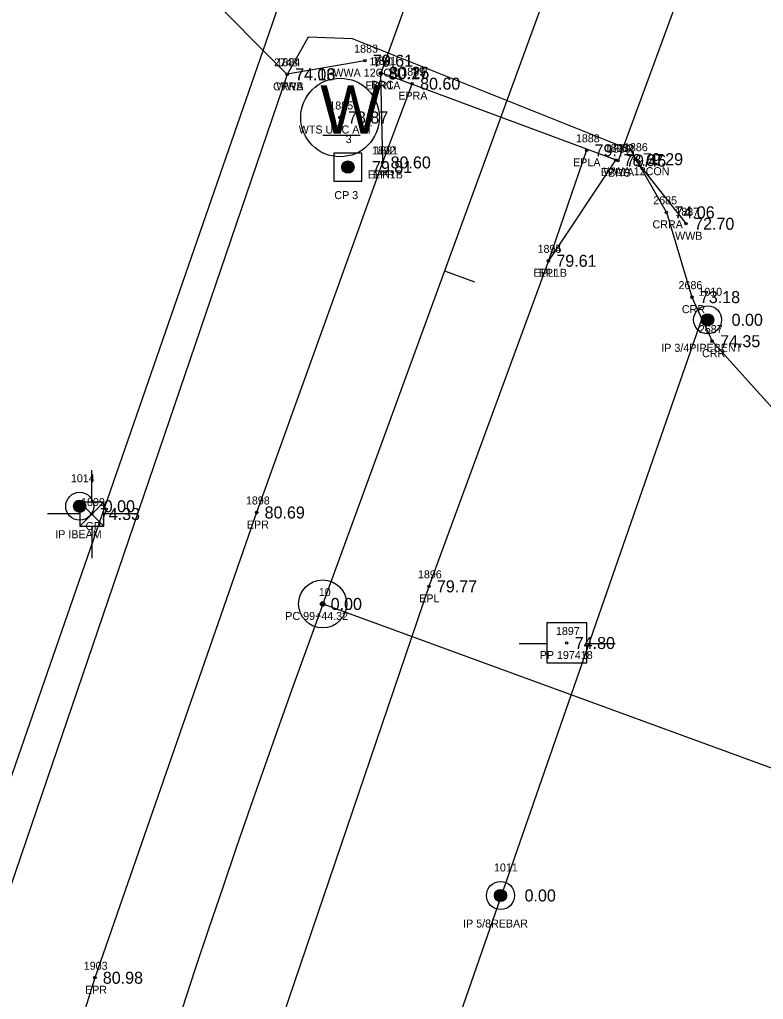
# Model space of a CAD drawing. Extents: x 2139392 to 2143384, y 505395 to 510520.
# Drawn here: x 2140632.7 to 2140725.6, y 508219 to 508341.4 of the extents above; entities that cross this region are included whole.
import ezdxf

# ---------------------------------------------------------------- set-up
doc = ezdxf.new("R2010")
doc.units = 0
for name, color, linetype in [('RD_EV_EX_Wetlands', 7, 'Continuous'), ('RD_EX_Bridge', 7, 'Continuous'), ('RD_EX_Bridge_txCode', 7, 'Continuous'), ('RD_EX_DV_Prop_txCode', 7, 'Continuous'), ('RD_EX_DV_PropPin', 7, 'Continuous'), ('RD_EX_H2O', 7, 'Continuous'), ('RD_EX_H2O_txCode', 7, 'Continuous'), ('RD_EX_Road', 7, 'Continuous'), ('RD_EX_Road_txCode', 7, 'Continuous'), ('RD_EX_TX_Bridge_ELEV', 7, 'Continuous'), ('RD_EX_TX_DV_Prop_ELEV', 7, 'Continuous'), ('RD_EX_TX_H2O_ELEV', 7, 'Continuous'), ('RD_EX_TX_Road_ELEV', 7, 'Continuous'), ('RD_EX_TX_UT_ELEV', 7, 'Continuous'), ('RD_EX_UT', 7, 'Continuous'), ('RD_EX_UT_txCode', 7, 'Continuous'), ('RD_EX_VEG', 7, 'Continuous'), ('RD_HC_Cl', 7, 'Continuous'), ('RD_HC_Data', 7, 'Continuous'), ('RD_HC_Data_Tic', 7, 'Continuous'), ('RD_HC_Survey', 7, 'Continuous'), ('RD_HC_Survey_ELEV', 7, 'Continuous'), ('RD_HC_Survey_txCode', 7, 'Continuous'), ('RD_HC_txCode', 7, 'Continuous'), ('RD_SMD_Locator', 7, 'Continuous')]:
    doc.layers.add(name, color=color, linetype=linetype)

msp = doc.modelspace()

# ---------------------------------------------------------------- linework, layer by layer
at = {"layer": 'RD_EV_EX_Wetlands'}
for points in [[(2141075.3, 509306.14), (2141106.63, 509288.93), (2141187.92, 509247.51), (2140965, 508598.64), (2140811.93, 508219.91), (2140776.47, 508059.54), (2140705.92, 508079.01), (2140681.94, 508086.65), (2140661.45, 508087.99), (2140646.39, 508098.18), (2140717.89, 508303.96)], [(2140713.45, 508317.31), (2140709, 508325.07), (2140674.24, 508339.01), (2140668.68, 508339.19), (2140666.06, 508334.55)], [(2140666.06, 508334.55), (2140628.92, 508225.59), (2140611.92, 508171.57), (2140593.56, 508103.81)], [(2140713.45, 508317.31), (2140716.63, 508306.71), (2140717.89, 508303.96)]]:
    msp.add_lwpolyline(points, dxfattribs=at)
at = {"layer": 'RD_EX_Bridge'}
for p, q in [((2140675.78, 508336.26), (2140666.09, 508334.57)), ((2140709.51, 508323.95), (2140715.91, 508315.88))]:
    msp.add_line(p, q, dxfattribs=at)
msp.add_lwpolyline([(2140701.08, 508399.16), (2140731.05, 508388.06), (2140707.41, 508323.76), (2140677.81, 508334.75), (2140701.08, 508399.16)], dxfattribs=at)
at = {"layer": 'RD_EX_DV_PropPin'}
for p, q in [((2140718.27, 508303.19), (2140718.27, 508304.57)), ((2140718.3, 508303.17), (2140718.3, 508304.59)), ((2140718.34, 508303.16), (2140718.34, 508304.6)), ((2140718.37, 508303.15), (2140718.37, 508304.61)), ((2140718.41, 508303.14), (2140718.41, 508304.62)), ((2140718.45, 508303.13), (2140718.45, 508304.63)), ((2140718.48, 508303.13), (2140718.48, 508304.63)), ((2140718.52, 508303.12), (2140718.52, 508304.64)), ((2140718.55, 508303.12), (2140718.55, 508304.64)), ((2140718.59, 508303.12), (2140718.59, 508304.64)), ((2140718.62, 508303.12), (2140718.62, 508304.64)), ((2140718.66, 508303.12), (2140718.66, 508304.64)), ((2140718.69, 508303.13), (2140718.69, 508304.63)), ((2140718.73, 508303.13), (2140718.73, 508304.63)), ((2140718.76, 508303.14), (2140718.76, 508304.62)), ((2140718.8, 508303.15), (2140718.8, 508304.61)), ((2140718.83, 508303.16), (2140718.83, 508304.6)), ((2140718.87, 508303.17), (2140718.87, 508304.59)), ((2140718.9, 508303.19), (2140718.9, 508304.57)), ((2140717.85, 508303.68), (2140717.85, 508304.08)), ((2140717.88, 508303.58), (2140717.88, 508304.18)), ((2140717.92, 508303.51), (2140717.92, 508304.25)), ((2140717.95, 508303.45), (2140717.95, 508304.31)), ((2140717.99, 508303.41), (2140717.99, 508304.35)), ((2140718.02, 508303.37), (2140718.02, 508304.4)), ((2140718.06, 508303.33), (2140718.06, 508304.43)), ((2140718.09, 508303.3), (2140718.09, 508304.46)), ((2140718.13, 508303.27), (2140718.13, 508304.49)), ((2140718.16, 508303.25), (2140718.16, 508304.52)), ((2140718.2, 508303.22), (2140718.2, 508304.54)), ((2140718.23, 508303.2), (2140718.23, 508304.56)), ((2140718.94, 508303.2), (2140718.94, 508304.56)), ((2140718.97, 508303.22), (2140718.97, 508304.54)), ((2140719.01, 508303.25), (2140719.01, 508304.52)), ((2140719.04, 508303.27), (2140719.04, 508304.49)), ((2140719.08, 508303.3), (2140719.08, 508304.46)), ((2140719.11, 508303.33), (2140719.11, 508304.43)), ((2140719.15, 508303.37), (2140719.15, 508304.4)), ((2140719.18, 508303.41), (2140719.18, 508304.35)), ((2140719.22, 508303.45), (2140719.22, 508304.31)), ((2140719.25, 508303.51), (2140719.25, 508304.25)), ((2140719.29, 508303.58), (2140719.29, 508304.18)), ((2140719.32, 508303.68), (2140719.32, 508304.08)), ((2140639.95, 508279.85), (2140639.95, 508281.32)), ((2140639.99, 508279.84), (2140639.99, 508281.33)), ((2140640.02, 508279.84), (2140640.02, 508281.33)), ((2140640.06, 508279.83), (2140640.06, 508281.34)), ((2140640.09, 508279.83), (2140640.09, 508281.34)), ((2140640.13, 508279.82), (2140640.13, 508281.35)), ((2140640.16, 508279.82), (2140640.16, 508281.35)), ((2140640.2, 508279.82), (2140640.2, 508281.35)), ((2140640.23, 508279.83), (2140640.23, 508281.34)), ((2140640.27, 508279.83), (2140640.27, 508281.34)), ((2140640.3, 508279.84), (2140640.3, 508281.33)), ((2140640.34, 508279.84), (2140640.34, 508281.33)), ((2140640.37, 508279.85), (2140640.37, 508281.32)), ((2140639.43, 508280.39), (2140639.43, 508280.78)), ((2140639.46, 508280.29), (2140639.46, 508280.88)), ((2140639.5, 508280.22), (2140639.5, 508280.95)), ((2140639.53, 508280.16), (2140639.53, 508281.01)), ((2140639.57, 508280.11), (2140639.57, 508281.06)), ((2140639.6, 508280.07), (2140639.6, 508281.1)), ((2140639.64, 508280.03), (2140639.64, 508281.14)), ((2140639.67, 508280), (2140639.67, 508281.17)), ((2140639.71, 508279.97), (2140639.71, 508281.19)), ((2140639.74, 508279.95), (2140639.74, 508281.22)), ((2140639.78, 508279.93), (2140639.78, 508281.24)), ((2140639.81, 508279.91), (2140639.81, 508281.26)), ((2140639.85, 508279.89), (2140639.85, 508281.28)), ((2140639.88, 508279.88), (2140639.88, 508281.29)), ((2140639.92, 508279.86), (2140639.92, 508281.31)), ((2140640.41, 508279.86), (2140640.41, 508281.31)), ((2140640.44, 508279.88), (2140640.44, 508281.29)), ((2140640.48, 508279.89), (2140640.48, 508281.28)), ((2140640.51, 508279.91), (2140640.51, 508281.26)), ((2140640.55, 508279.93), (2140640.55, 508281.24)), ((2140640.58, 508279.95), (2140640.58, 508281.22)), ((2140640.62, 508279.97), (2140640.62, 508281.19)), ((2140640.65, 508280), (2140640.65, 508281.17)), ((2140640.69, 508280.03), (2140640.69, 508281.14)), ((2140640.72, 508280.07), (2140640.72, 508281.1)), ((2140640.76, 508280.11), (2140640.76, 508281.06)), ((2140640.79, 508280.16), (2140640.79, 508281.01)), ((2140640.83, 508280.22), (2140640.83, 508280.95)), ((2140640.86, 508280.29), (2140640.86, 508280.88)), ((2140640.9, 508280.39), (2140640.9, 508280.78)), ((2140692.1, 508231.51), (2140692.1, 508232.37)), ((2140692.14, 508231.46), (2140692.14, 508232.41)), ((2140692.17, 508231.42), (2140692.17, 508232.45)), ((2140692.21, 508231.39), (2140692.21, 508232.49)), ((2140692.24, 508231.36), (2140692.24, 508232.52)), ((2140692.28, 508231.33), (2140692.28, 508232.55)), ((2140692.31, 508231.3), (2140692.31, 508232.57)), ((2140692.35, 508231.28), (2140692.35, 508232.59)), ((2140692.38, 508231.26), (2140692.38, 508232.61)), ((2140692.42, 508231.25), (2140692.42, 508232.63)), ((2140692.45, 508231.23), (2140692.45, 508232.65)), ((2140692.49, 508231.22), (2140692.49, 508232.66)), ((2140692.52, 508231.21), (2140692.52, 508232.67)), ((2140692.56, 508231.2), (2140692.56, 508232.68)), ((2140692.59, 508231.19), (2140692.59, 508232.69)), ((2140692.63, 508231.18), (2140692.63, 508232.69)), ((2140692.66, 508231.18), (2140692.66, 508232.7)), ((2140692.7, 508231.18), (2140692.7, 508232.7)), ((2140692.73, 508231.18), (2140692.73, 508232.7)), ((2140692.77, 508231.18), (2140692.77, 508232.7)), ((2140692.8, 508231.18), (2140692.8, 508232.7)), ((2140692.84, 508231.18), (2140692.84, 508232.69)), ((2140692.87, 508231.19), (2140692.87, 508232.69)), ((2140692.91, 508231.2), (2140692.91, 508232.68)), ((2140692.94, 508231.21), (2140692.94, 508232.67)), ((2140692.98, 508231.22), (2140692.98, 508232.66)), ((2140693.01, 508231.23), (2140693.01, 508232.65)), ((2140693.05, 508231.25), (2140693.05, 508232.63)), ((2140693.08, 508231.26), (2140693.08, 508232.61)), ((2140693.12, 508231.28), (2140693.12, 508232.59)), ((2140693.15, 508231.3), (2140693.15, 508232.57)), ((2140693.19, 508231.33), (2140693.19, 508232.55)), ((2140693.22, 508231.36), (2140693.22, 508232.52)), ((2140693.26, 508231.39), (2140693.26, 508232.49)), ((2140693.29, 508231.42), (2140693.29, 508232.45)), ((2140693.33, 508231.46), (2140693.33, 508232.41)), ((2140693.36, 508231.51), (2140693.36, 508232.37)), ((2140692, 508231.74), (2140692, 508232.13)), ((2140692.03, 508231.64), (2140692.03, 508232.24)), ((2140692.07, 508231.57), (2140692.07, 508232.31)), ((2140693.4, 508231.57), (2140693.4, 508232.31)), ((2140693.43, 508231.64), (2140693.43, 508232.24)), ((2140693.47, 508231.74), (2140693.47, 508232.13))]:
    msp.add_line(p, q, dxfattribs=at)
for centre, radius in [((2140718.59, 508303.88), 1.75), ((2140718.59, 508303.88), 0.761), ((2140640.16, 508280.58), 1.75), ((2140640.16, 508280.58), 0.761), ((2140692.73, 508231.94), 1.75), ((2140692.73, 508231.94), 0.761)]:
    msp.add_circle(centre, radius, dxfattribs=at)
at = {"layer": 'RD_EX_H2O'}
for points in [[(2140666.06, 508334.55), (2140601.63, 508399.26), (2140555.06, 508452.56), (2140445.76, 508456.93), (2140394.38, 508460.34), (2140330.91, 508434.11), (2140238.02, 508387.64)], [(2140713.45, 508317.31), (2140716.63, 508306.71), (2140719.15, 508301.21), (2140737.29, 508281.1), (2140744.57, 508269.75), (2140792.9, 508190.84), (2140777.01, 508138.14), (2140787.07, 508130.01), (2140775.85, 508060.07), (2140818.22, 508047.21), (2140904.79, 508019.19), (2140978.29, 507974.61), (2141008.29, 508005.21), (2141024.7, 508023.32), (2141105.3, 508022.5)]]:
    msp.add_lwpolyline(points, dxfattribs=at)
at = {"layer": 'RD_EX_Road'}
for p, q in [((2140677.72, 508334.66), (2140678, 508323.55)), ((2140707.1, 508323.84), (2140698.7, 508311.25))]:
    msp.add_line(p, q, dxfattribs=at)
for points in [[(2140681.68, 508333.39), (2140678, 508323.55), (2140662.26, 508279.8), (2140642.05, 508221.66), (2140625.62, 508169.11), (2140610.77, 508115.59), (2140598.26, 508062.62), (2140587.77, 508011.95), (2140578.4, 507958.88), (2140570.83, 507901.38), (2140564.91, 507841.03), (2140561.47, 507785.62), (2140559.81, 507732.33), (2140559.74, 507699.59), (2140559.81, 507681.93)], [(2140703.48, 508325.06), (2140698.7, 508311.25), (2140683.78, 508270.57), (2140664.74, 508214.51), (2140648.33, 508161.68), (2140633.75, 508109.58), (2140620.84, 508055.69), (2140611.2, 508005.95), (2140602.32, 507955.16), (2140596.37, 507899.44), (2140590.47, 507838.04), (2140586.94, 507784.96), (2140586.53, 507754.79), (2140583.43, 507730.59), (2140583.94, 507673.5)]]:
    msp.add_lwpolyline(points, dxfattribs=at)
at = {"layer": 'RD_EX_UT'}
for p, q in [((2140670.55, 508326.96), (2140675.18, 508326.96)), ((2140641.67, 508281.11), (2140641.67, 508285.11)), ((2140643.17, 508281.11), (2140640.17, 508278.11)), ((2140640.17, 508281.11), (2140643.17, 508278.11)), ((2140643.17, 508281.11), (2140640.17, 508281.11)), ((2140640.17, 508281.11), (2140640.17, 508278.11)), ((2140643.17, 508278.11), (2140643.17, 508281.11)), ((2140640.15, 508279.65), (2140636.15, 508279.65)), ((2140643.19, 508279.67), (2140647.2, 508279.67)), ((2140640.17, 508278.11), (2140643.17, 508278.11)), ((2140641.67, 508278.11), (2140641.67, 508274.11)), ((2140703.49, 508266), (2140698.49, 508266)), ((2140698.49, 508266), (2140698.49, 508261)), ((2140703.49, 508261), (2140703.49, 508266)), ((2140695.06, 508263.44), (2140698.52, 508263.44)), ((2140703.42, 508263.44), (2140707.06, 508263.44)), ((2140698.49, 508261), (2140703.49, 508261))]:
    msp.add_line(p, q, dxfattribs=at)
msp.add_circle((2140672.68, 508329.16), 4.91, dxfattribs=at)
at = {"layer": 'RD_EX_VEG'}
msp.add_lwpolyline([(2140900.08, 509397.36), (2141021.29, 509326.2), (2140852.61, 508865.26), (2140689.34, 508413.46), (2140624.53, 508226.48), (2140606.41, 508171.78), (2140591.23, 508116.67), (2140558.82, 507962.77), (2140538.78, 507709.07), (2140410.61, 507724.88)], dxfattribs=at)
at = {"layer": 'RD_HC_Cl'}
msp.add_line((2141333.53, 510081.69), (2140670.51, 508268.37), dxfattribs=at)
msp.add_arc((2142207.96, 507706.22), 1636.99, 159.91581, 183.89148, dxfattribs=at)
at = {"layer": 'RD_HC_Data'}
msp.add_line((2140670.51, 508268.37), (2140779.99, 508228.34), dxfattribs=at)
for radius in [3, 0.282]:
    msp.add_circle((2140670.51, 508268.37), radius, dxfattribs=at)
at = {"layer": 'RD_HC_Data_Tic'}
msp.add_line((2140685.73, 508309.99), (2140689.49, 508308.62), dxfattribs=at)
at = {"layer": 'RD_HC_Survey'}
for p, q in [((2140672.92, 508322.79), (2140672.92, 508323.14)), ((2140672.95, 508322.7), (2140672.95, 508323.23)), ((2140672.97, 508322.64), (2140672.97, 508323.29)), ((2140672.99, 508322.59), (2140672.99, 508323.34)), ((2140673.02, 508322.55), (2140673.02, 508323.38)), ((2140673.04, 508322.52), (2140673.04, 508323.41)), ((2140673.07, 508322.48), (2140673.07, 508323.45)), ((2140673.09, 508322.45), (2140673.09, 508323.48)), ((2140673.12, 508322.43), (2140673.12, 508323.5)), ((2140673.14, 508322.4), (2140673.14, 508323.53)), ((2140673.17, 508322.38), (2140673.17, 508323.55)), ((2140673.19, 508322.36), (2140673.19, 508323.57)), ((2140673.22, 508322.34), (2140673.22, 508323.59)), ((2140673.24, 508322.32), (2140673.24, 508323.6)), ((2140673.27, 508322.31), (2140673.27, 508323.62)), ((2140673.29, 508322.29), (2140673.29, 508323.64)), ((2140673.32, 508322.28), (2140673.32, 508323.65)), ((2140673.34, 508322.27), (2140673.34, 508323.66)), ((2140673.37, 508322.26), (2140673.37, 508323.67)), ((2140673.39, 508322.25), (2140673.39, 508323.68)), ((2140673.42, 508322.24), (2140673.42, 508323.69)), ((2140673.44, 508322.23), (2140673.44, 508323.7)), ((2140673.46, 508322.22), (2140673.46, 508323.71)), ((2140673.49, 508322.22), (2140673.49, 508323.71)), ((2140673.51, 508322.21), (2140673.51, 508323.72)), ((2140673.54, 508322.21), (2140673.54, 508323.72)), ((2140673.56, 508322.2), (2140673.56, 508323.73)), ((2140673.59, 508322.2), (2140673.59, 508323.73)), ((2140673.61, 508322.2), (2140673.61, 508323.73)), ((2140673.64, 508322.2), (2140673.64, 508323.73)), ((2140673.66, 508322.2), (2140673.66, 508323.73)), ((2140673.69, 508322.2), (2140673.69, 508323.73)), ((2140673.71, 508322.2), (2140673.71, 508323.73)), ((2140673.74, 508322.2), (2140673.74, 508323.73)), ((2140673.76, 508322.2), (2140673.76, 508323.73)), ((2140673.79, 508322.2), (2140673.79, 508323.73)), ((2140673.81, 508322.21), (2140673.81, 508323.72)), ((2140673.84, 508322.21), (2140673.84, 508323.72)), ((2140673.86, 508322.22), (2140673.86, 508323.71)), ((2140673.89, 508322.23), (2140673.89, 508323.7)), ((2140673.91, 508322.23), (2140673.91, 508323.7)), ((2140673.93, 508322.24), (2140673.93, 508323.69)), ((2140673.96, 508322.25), (2140673.96, 508323.68)), ((2140673.98, 508322.26), (2140673.98, 508323.67)), ((2140674.01, 508322.27), (2140674.01, 508323.65)), ((2140674.03, 508322.29), (2140674.03, 508323.64)), ((2140674.06, 508322.3), (2140674.06, 508323.63)), ((2140674.08, 508322.32), (2140674.08, 508323.61)), ((2140674.11, 508322.33), (2140674.11, 508323.6)), ((2140674.13, 508322.35), (2140674.13, 508323.58)), ((2140674.16, 508322.37), (2140674.16, 508323.56)), ((2140674.18, 508322.39), (2140674.18, 508323.54)), ((2140674.21, 508322.42), (2140674.21, 508323.51)), ((2140674.23, 508322.44), (2140674.23, 508323.49)), ((2140674.26, 508322.47), (2140674.26, 508323.46)), ((2140674.28, 508322.5), (2140674.28, 508323.43)), ((2140674.31, 508322.53), (2140674.31, 508323.4)), ((2140674.33, 508322.57), (2140674.33, 508323.36)), ((2140674.36, 508322.62), (2140674.36, 508323.31)), ((2140674.38, 508322.67), (2140674.38, 508323.26)), ((2140674.41, 508322.74), (2140674.41, 508323.19)), ((2140674.43, 508322.85), (2140674.43, 508323.08))]:
    msp.add_line(p, q, dxfattribs=at)
msp.add_lwpolyline([(2140675.42, 508324.71), (2140671.92, 508324.71), (2140671.92, 508321.21), (2140675.42, 508321.21)], close=True, dxfattribs=at)
msp.add_circle((2140673.67, 508322.96), 0.769, dxfattribs=at)
at = {"layer": 'RD_SMD_Locator'}
for centre in [(2140675.78, 508336.26), (2140666.06, 508334.55), (2140666.09, 508334.57), (2140677.72, 508334.66), (2140677.81, 508334.75), (2140681.68, 508333.39), (2140672.68, 508329.16), (2140703.48, 508325.06), (2140673.67, 508322.96), (2140678, 508323.55), (2140678, 508323.55), (2140707.1, 508323.84), (2140707.41, 508323.76), (2140709.51, 508323.95), (2140713.45, 508317.31), (2140715.91, 508315.88), (2140698.7, 508311.25), (2140698.7, 508311.25), (2140716.63, 508306.71), (2140718.59, 508303.88), (2140719.15, 508301.21), (2140640.16, 508280.58), (2140641.67, 508279.61), (2140662.26, 508279.8), (2140683.78, 508270.57), (2140670.51, 508268.37), (2140701, 508263.49), (2140692.73, 508231.94), (2140642.05, 508221.66)]:
    msp.add_circle(centre, 0.15, dxfattribs=at)

# ---------------------------------------------------------------- texts
at = {"layer": 'RD_EX_Bridge_txCode'}
for s, p in [('1883', (2140674.44, 508337.26)), ('1884', (2140664.74, 508335.57)), ('1881', (2140676.75, 508335.75)), ('WWA 12CON', (2140671.85, 508334.26)), ('WWB', (2140664.71, 508332.57)), ('BRC', (2140676.56, 508332.75)), ('1880', (2140706.02, 508324.76)), ('1886', (2140708.14, 508324.95)), ('WWA 12CON', (2140705.58, 508321.95)), ('BRC', (2140706.16, 508321.76)), ('1887', (2140714.56, 508316.88)), ('WWB', (2140714.53, 508313.88))]:
    msp.add_text(s, height=1, dxfattribs=at).set_placement(p)
at = {"layer": 'RD_EX_DV_Prop_txCode'}
for s, p in [('1010', (2140717.44, 508306.88)), ('IP 3/4PIPEBENT', (2140712.81, 508299.88)), ('1014', (2140639.06, 508283.58)), ('IP IBEAM', (2140637.11, 508276.58)), ('1011', (2140691.91, 508234.94)), ('IP 5/8REBAR', (2140688.05, 508227.94))]:
    msp.add_text(s, height=1, dxfattribs=at).set_placement(p)
at = {"layer": 'RD_EX_H2O_txCode'}
for s, p in [('2743', (2140664.43, 508335.55)), ('CRRA', (2140664.31, 508332.55)), ('2685', (2140711.8, 508318.31)), ('CRRA', (2140711.71, 508315.31)), ('2686', (2140714.96, 508307.71)), ('CRR', (2140715.38, 508304.71)), ('2687', (2140717.5, 508302.21)), ('CRR', (2140717.9, 508299.21))]:
    msp.add_text(s, height=1, dxfattribs=at).set_placement(p)
at = {"layer": 'RD_EX_Road_txCode'}
for s, p in [('1890', (2140676.34, 508335.66)), ('1889', (2140680.33, 508334.39)), ('EPR1A', (2140675.84, 508332.66)), ('EPRA', (2140679.96, 508331.39)), ('1888', (2140702.14, 508326.06)), ('1892', (2140676.66, 508324.55)), ('1891', (2140676.94, 508324.55)), ('1893', (2140705.75, 508324.84)), ('EPLA', (2140701.79, 508323.06)), ('EPR1B', (2140676.14, 508321.55)), ('EPR', (2140676.78, 508321.55)), ('EPL1A', (2140705.24, 508321.84)), ('1894', (2140697.35, 508312.25)), ('1895', (2140697.35, 508312.25)), ('EPL1B', (2140696.86, 508309.25)), ('EPL', (2140697.5, 508309.25)), ('1898', (2140660.92, 508280.8)), ('EPR', (2140661.04, 508277.8)), ('1896', (2140682.41, 508271.57)), ('EPL', (2140682.57, 508268.57)), ('1903', (2140640.67, 508222.66)), ('EPR', (2140640.82, 508219.66))]:
    msp.add_text(s, height=1, dxfattribs=at).set_placement(p)
at = {"layer": 'RD_EX_TX_Bridge_ELEV'}
for s, p in [('79.61', (2140676.78, 508335.51)), ('74.16', (2140667.09, 508333.82)), ('80.26', (2140678.81, 508334)), ('79.46', (2140708.41, 508323.01)), ('79.29', (2140710.51, 508323.2)), ('72.70', (2140716.91, 508315.13))]:
    msp.add_text(s, height=1.5, dxfattribs=at).set_placement(p)
at = {"layer": 'RD_EX_TX_DV_Prop_ELEV'}
for p in [(2140721.59, 508303.13), (2140643.16, 508279.83), (2140695.73, 508231.19)]:
    msp.add_text('0.00', height=1.5, dxfattribs=at).set_placement(p)
at = {"layer": 'RD_EX_TX_H2O_ELEV'}
for s, p in [('74.03', (2140667.06, 508333.8)), ('74.06', (2140714.45, 508316.56)), ('73.18', (2140717.63, 508305.96)), ('74.35', (2140720.15, 508300.46))]:
    msp.add_text(s, height=1.5, dxfattribs=at).set_placement(p)
at = {"layer": 'RD_EX_TX_Road_ELEV'}
for s, p in [('80.17', (2140678.72, 508333.91)), ('80.60', (2140682.68, 508332.64)), ('79.73', (2140704.48, 508324.31)), ('80.60', (2140679, 508322.8)), ('80.60', (2140679, 508322.8)), ('78.67', (2140708.1, 508323.09)), ('79.61', (2140699.7, 508310.5)), ('79.61', (2140699.7, 508310.5)), ('80.69', (2140663.26, 508279.05)), ('79.77', (2140684.78, 508269.82)), ('80.98', (2140643.05, 508220.91))]:
    msp.add_text(s, height=1.5, dxfattribs=at).set_placement(p)
at = {"layer": 'RD_EX_TX_UT_ELEV'}
for s, p in [('78.87', (2140673.68, 508328.41)), ('74.33', (2140642.67, 508278.86))]:
    msp.add_text(s, height=1.5, dxfattribs=at).set_placement(p)
at = {"layer": 'RD_EX_UT'}
msp.add_text('W', height=6, dxfattribs=at).set_placement((2140670.22, 508327.16))
at = {"layer": 'RD_EX_UT_txCode'}
for s, p in [('1885', (2140671.34, 508330.16)), ('WTS UGC ATT', (2140667.52, 508327.16)), ('1899', (2140640.33, 508280.61)), ('GP', (2140640.89, 508277.61)), ('1897', (2140699.65, 508264.49)), ('PP 197418', (2140697.62, 508261.49))]:
    msp.add_text(s, height=1, dxfattribs=at).set_placement(p)
at = {"layer": 'RD_HC_Data'}
msp.add_text('S 40%%d 03\' 01" E', height=6, rotation=310.0502, dxfattribs=at).set_placement((2140723.05, 508358.08))
at = {"layer": 'RD_HC_Survey_ELEV'}
for s, p in [('79.81', (2140676.67, 508322.21)), ('0.00', (2140671.51, 508267.62)), ('74.80', (2140702, 508262.74))]:
    msp.add_text(s, height=1.5, dxfattribs=at).set_placement(p)
at = {"layer": 'RD_HC_Survey_txCode'}
for s, p in [('3', (2140673.39, 508325.96)), ('CP 3', (2140671.97, 508318.96))]:
    msp.add_text(s, height=1, dxfattribs=at).set_placement(p)
at = {"layer": 'RD_HC_txCode'}
for s, p in [('10', (2140670.03, 508269.37)), ('PC 99+44.32', (2140665.84, 508266.37))]:
    msp.add_text(s, height=1, dxfattribs=at).set_placement(p)

doc.saveas('drawing.dxf')
